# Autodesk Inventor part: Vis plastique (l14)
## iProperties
Author: Flavien MARTY
Shininess: 60.0
PropertySet Name: _Private Model Information
Created: 2001-10
Part Number: Vis plastique (l14)
Material: Par défaut
Document SubType Name: Modélisation
Designer: Flavien MARTY
Control State: 0
Master: False
Checked Out: False
PropertySet Name: Design Tracking Control
Density: 0.0
Volumn: 0.0
Area: 0.0
PropertySet Name: Model Information
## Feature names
1. Base1
